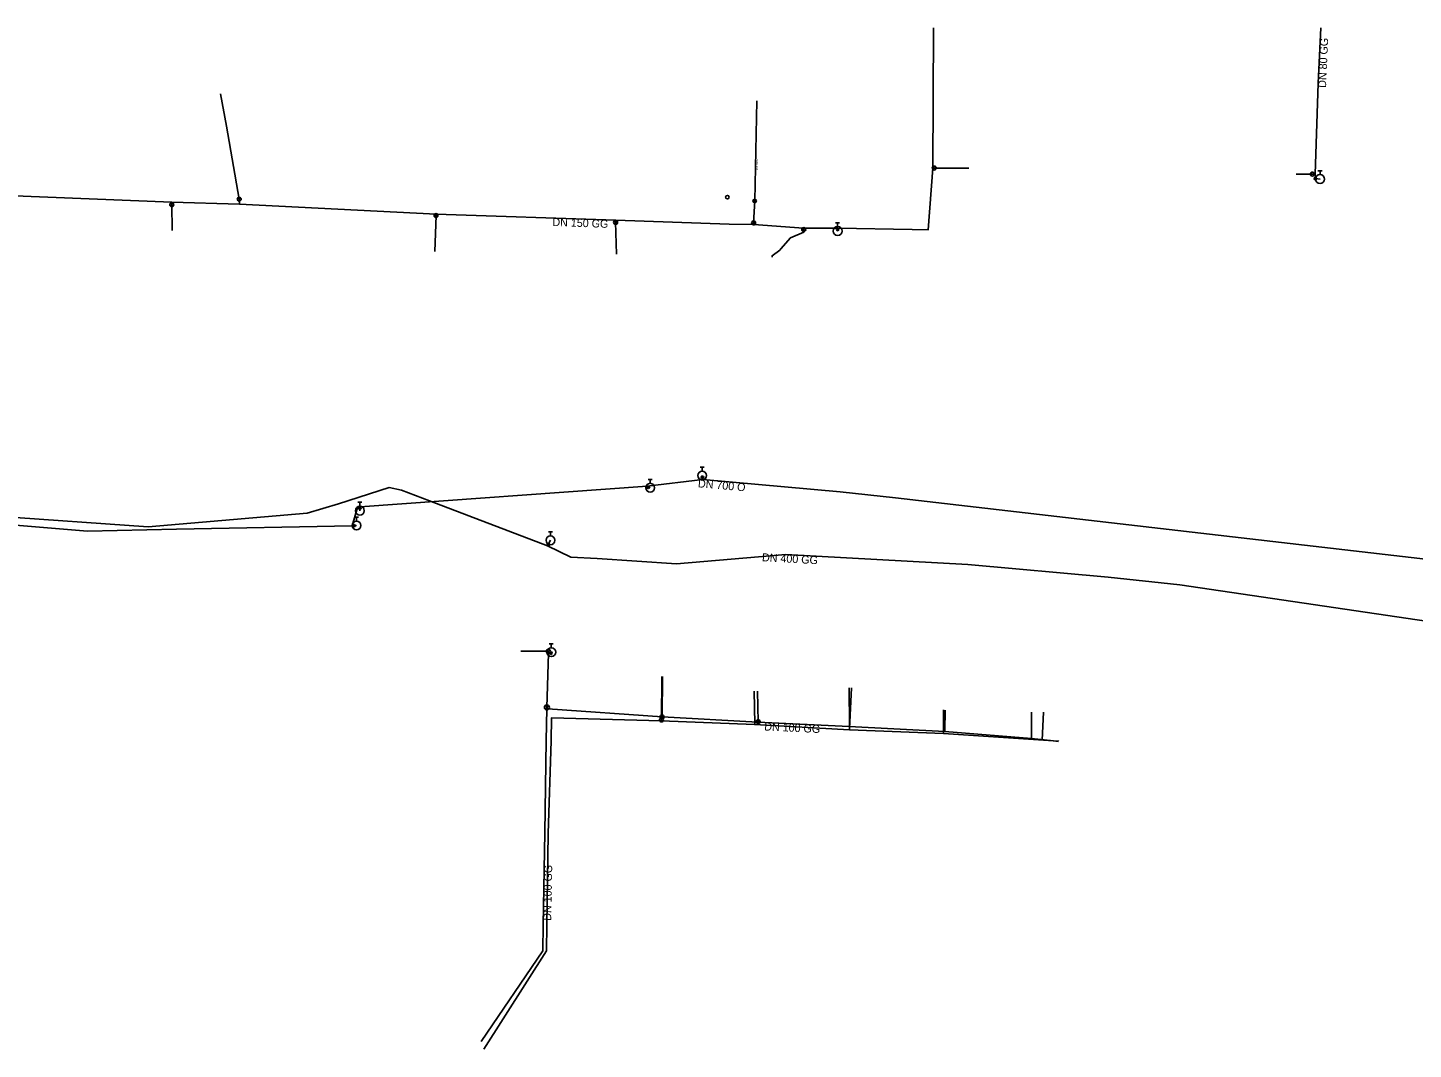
# Model space of a CAD drawing. Extents: x -451355 to -449353, y -1101368 to -1101089.
# Drawn here: x -451062.3 to -450784.4, y -1101294 to -1101089.2 of the extents above; entities that cross this region are included whole.
import ezdxf

# ---------------------------------------------------------------- set-up
doc = ezdxf.new("R2010")
doc.units = 0
for name, color, linetype in [('_hydrantova_odbocka_', 7, 'Continuous'), ('_pripojka_prevzato_z_dokumentace_', 7, 'Continuous'), ('_pripojka_priblizne_', 7, 'Continuous'), ('_voda_smvak_prevzato_z_dokumentace_', 7, 'Continuous'), ('Default', 7, 'Continuous'), ('MoLevel 27', 7, 'Continuous'), ('MoLevel 28', 7, 'Continuous'), ('MoLevel 30', 7, 'Continuous'), ('MoLevel 46', 7, 'Continuous'), ('MoLevel 53', 7, 'Continuous'), ('MoLevel 55', 7, 'Continuous')]:
    doc.layers.add(name, color=color, linetype=linetype)

# ---------------------------------------------------------------- blocks, each defined once
blk = doc.blocks.new('_uzaver_')
at = {"layer": 'Default'}
for p, q in [((-0.000035, -0.000035), (0.000035, 0.000035)), ((0.000035, -0.000035), (-0.000035, 0.000035))]:
    blk.add_line(p, q, dxfattribs=at)
for radius in [0.00005, 0.0000025]:
    blk.add_circle((0, 0), radius, dxfattribs=at)
blk = doc.blocks.new('_uzaver_pripojka_')
at = {"layer": 'Default'}
for p, q in [((-0.000035, -0.000035), (0.000035, 0.000035)), ((0.000035, -0.000035), (-0.000035, 0.000035))]:
    blk.add_line(p, q, dxfattribs=at)
for radius in [0.00005, 0.0000025]:
    blk.add_circle((0, 0), radius, dxfattribs=at)
blk = doc.blocks.new('_hydrant_voda_')
at = {"layer": 'Default'}
for p, q in [((-0.000023, 0.000095), (0.000023, 0.000095)), ((0, 0.000095), (0, 0.00005))]:
    blk.add_line(p, q, dxfattribs=at)
blk.add_circle((0, 0), 0.00005, dxfattribs=at)
blk = doc.blocks.new('_sachta_voda_')
at = {"layer": 'Default'}
blk.add_circle((0, 0), 0.000035, dxfattribs=at)

msp = doc.modelspace()

# ---------------------------------------------------------------- linework, layer by layer
at = {"layer": '_hydrantova_odbocka_'}
for p, q in [((-450804.06, -1101119.44), (-450803.13, -1101119.53)), ((-450957.85, -1101214.57), (-450957.34, -1101214.56)), ((-450957.34, -1101214.56), (-450957.28, -1101214.38))]:
    msp.add_line(p, q, dxfattribs=at)
for points in [[(-450899.84, -1101129.39), (-450899.84, -1101129.63), (-450899.86, -1101129.95)], [(-450938.03, -1101181.08), (-450938.05, -1101181.35), (-450937.85, -1101181.33), (-450937.44, -1101181.41)], [(-450926.89, -1101179.79), (-450926.96, -1101179.31), (-450927.03, -1101178.98)], [(-450995.63, -1101185.21), (-450995.68, -1101185.47), (-450995.66, -1101186.01)], [(-450997.22, -1101189.02), (-450996.84, -1101189.02), (-450996.33, -1101188.99)], [(-450958.04, -1101193.09), (-450957.88, -1101192.79), (-450957.46, -1101191.95)]]:
    msp.add_lwpolyline(points, dxfattribs=at)
at = {"layer": '_pripojka_prevzato_z_dokumentace_'}
for p, q in [((-450916.49, -1101123.92), (-450916.03, -1101103.87)), ((-450962.34, -1101214.2), (-450963.4, -1101214.2)), ((-450935.08, -1101227.36), (-450934.99, -1101219.25))]:
    msp.add_line(p, q, dxfattribs=at)
for points in [[(-451019.78, -1101124.55), (-451019.87, -1101123.57), (-451022.41, -1101108.94), (-451023.59, -1101102.43)], [(-450880.8, -1101117.34), (-450880.5, -1101117.33), (-450873.58, -1101117.32)], [(-450804.12, -1101118.58), (-450804.14, -1101118.58), (-450804.66, -1101118.54), (-450807.94, -1101118.55)], [(-451033.37, -1101124.19), (-451033.39, -1101124.65), (-451033.32, -1101129.83)], [(-450916.66, -1101128.63), (-450916.7, -1101128.31), (-450916.49, -1101123.92)], [(-450980.4, -1101126.55), (-450980.4, -1101126.85), (-450980.66, -1101134.07)], [(-450944.34, -1101127.77), (-450944.38, -1101128.2), (-450944.21, -1101134.61)], [(-450906.69, -1101129.37), (-450906.67, -1101129.66), (-450906.64, -1101130.19), (-450909.32, -1101131.32), (-450911.24, -1101133.55)], [(-450911.24, -1101133.55), (-450911.47, -1101133.81), (-450913, -1101134.89), (-450913.01, -1101135.21)], [(-450957.85, -1101214.57), (-450957.87, -1101214.2), (-450962.34, -1101214.2)], [(-450935.24, -1101228.17), (-450935.19, -1101227.96), (-450935.11, -1101219.25)], [(-450916.51, -1101228.86), (-450916.48, -1101228.71), (-450916.61, -1101222.22)], [(-450915.83, -1101228.39), (-450915.81, -1101228.31), (-450915.9, -1101222.17)], [(-450897.52, -1101229.26), (-450897.51, -1101229.16), (-450897.58, -1101221.5)], [(-450897.5, -1101229.93), (-450897.5, -1101229.75), (-450897.05, -1101221.51)], [(-450878.66, -1101230.68), (-450878.63, -1101230.48), (-450878.63, -1101225.93)], [(-450878.37, -1101230.29), (-450878.36, -1101230.07), (-450878.31, -1101225.97)], [(-450861.01, -1101231.7), (-450861, -1101231.39), (-450861, -1101226.4)]]:
    msp.add_lwpolyline(points, dxfattribs=at)
at = {"layer": '_pripojka_priblizne_'}
msp.add_line((-450858.57, -1101226.38), (-450858.84, -1101232.01), dxfattribs=at)
at = {"layer": '_voda_smvak_prevzato_z_dokumentace_'}
for p, q in [((-450957.85, -1101214.57), (-450958.17, -1101225.45)), ((-450958.17, -1101225.45), (-450958.18, -1101225.73))]:
    msp.add_line(p, q, dxfattribs=at)
for points in [[(-450880.63, -1101089.19), (-450880.8, -1101117.34), (-450881.71, -1101129.74), (-450884.9, -1101129.62), (-450899.84, -1101129.39), (-450906.69, -1101129.37), (-450916.66, -1101128.63), (-450921.61, -1101128.6), (-450944.34, -1101127.77), (-450980.4, -1101126.55), (-451019.78, -1101124.55), (-451033.37, -1101124.19), (-451083.14, -1101122.14), (-451084.29, -1101121.78)], [(-450802.99, -1101089.19), (-450803.48, -1101100.3), (-450804.12, -1101118.58), (-450804.06, -1101119.44)], [(-451068.8, -1101188.58), (-451050.3, -1101190.14), (-451032.45, -1101189.7), (-450997.22, -1101189.02), (-450996.11, -1101185.36), (-450995.63, -1101185.21), (-450938.03, -1101181.08), (-450926.89, -1101179.79), (-450899.38, -1101182.22), (-450888.28, -1101183.45), (-450772.13, -1101196.87)], [(-451068.59, -1101187.08), (-451038.12, -1101189.24), (-451006.24, -1101186.52), (-450999.94, -1101184.64), (-450989.76, -1101181.39), (-450987.33, -1101181.88), (-450981.7, -1101184.05), (-450958.04, -1101193.09), (-450953.39, -1101195.36), (-450948.09, -1101195.61), (-450932.19, -1101196.67), (-450910.27, -1101194.8), (-450873.74, -1101196.81), (-450845.59, -1101199.31), (-450831.24, -1101200.86), (-450754.63, -1101212.14), (-450745.13, -1101214.06)], [(-450958.18, -1101225.73), (-450958.28, -1101232.06), (-450958.56, -1101250.61), (-450958.93, -1101269.01), (-450958.96, -1101274.22), (-450971.36, -1101292.42)], [(-450855.54, -1101232.28), (-450857.15, -1101232.11), (-450861.01, -1101231.7), (-450878.37, -1101230.29), (-450897.52, -1101229.26), (-450915.83, -1101228.39), (-450935.08, -1101227.36), (-450957.96, -1101225.75), (-450958.18, -1101225.73)], [(-450855.54, -1101232.25), (-450855.54, -1101232.2), (-450856.59, -1101232.16), (-450878.66, -1101230.68), (-450897.5, -1101229.93), (-450916.51, -1101228.86), (-450935.24, -1101228.17), (-450957.23, -1101227.52), (-450957.29, -1101232.18), (-450957.91, -1101250.71), (-450958.19, -1101269.04), (-450958.24, -1101274.22), (-450970.83, -1101293.98)]]:
    msp.add_lwpolyline(points, dxfattribs=at)

# ---------------------------------------------------------------- block references
at = {"layer": 'MoLevel 27', "xscale": 5000, "yscale": 5000}
for p in [(-450804.06, -1101119.44), (-450899.84, -1101129.63), (-450995.68, -1101185.47), (-450957.88, -1101192.79), (-450957.34, -1101214.56)]:
    msp.add_blockref('_uzaver_', p, dxfattribs=at)
at = {"layer": 'MoLevel 27'}
for p, xscale, yscale, rotation in [((-450937.85, -1101181.33), 5000, 4999.999999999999, -174.61629722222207), ((-450926.96, -1101179.31), 5000.000000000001, 5000, -80.92363333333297), ((-450996.84, -1101189.02), 5000, 5000.000000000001, -0.45835555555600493), ((-450958.17, -1101225.45), 10000, 10000.000000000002, -4.028702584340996)]:
    msp.add_blockref('_uzaver_', p, dxfattribs=dict(at, xscale=xscale, yscale=yscale, rotation=rotation))
at = {"layer": 'MoLevel 28', "xscale": 17636.68430335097, "yscale": 17636.68430335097}
for p in [(-450803.13, -1101119.53), (-450899.86, -1101129.95), (-450927.03, -1101178.98), (-450937.44, -1101181.41), (-450995.66, -1101186.01), (-450996.33, -1101188.99), (-450957.46, -1101191.95), (-450957.28, -1101214.38)]:
    msp.add_blockref('_hydrant_voda_', p, dxfattribs=at)
at = {"layer": 'MoLevel 30', "xscale": 10000, "yscale": 10000}
for p in [(-450921.97, -1101123.17), (-450916.49, -1101123.92)]:
    msp.add_blockref('_sachta_voda_', p, dxfattribs=at)
at = {"layer": 'MoLevel 53', "xscale": 7999.999999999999, "yscale": 7999.999999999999}
for p in [(-450880.5, -1101117.33), (-450804.66, -1101118.54), (-451019.87, -1101123.57), (-451033.39, -1101124.65), (-450980.4, -1101126.85), (-450944.38, -1101128.2), (-450916.7, -1101128.31), (-450906.67, -1101129.66), (-450957.87, -1101214.2), (-450935.19, -1101227.96), (-450935.08, -1101227.36), (-450915.81, -1101228.31)]:
    msp.add_blockref('_uzaver_pripojka_', p, dxfattribs=at)

# ---------------------------------------------------------------- texts
at = {"layer": 'MoLevel 46'}
for s, rotation, p in [('DN 80 GG', 87.4759, (-450801.92, -1101101.27)), ('DN 150 GG', 358.0623, (-450957.08, -1101128.94)), ('DN 700 O', 354.9461, (-450927.92, -1101181.31)), ('DN 400 GG', 356.8506, (-450915.06, -1101196.14)), ('DN 100 GG', 357.2796, (-450914.6, -1101230.06)), ('DN 100 GG', 88.848, (-450957.31, -1101268.23))]:
    msp.add_text(s, height=1.605, rotation=rotation, dxfattribs=at).set_placement(p)
at = {"layer": 'MoLevel 55'}
msp.add_text('DN 80 L', height=0.455, rotation=88.6827, dxfattribs=at).set_placement((-450915.89, -1101117.79))

doc.saveas('drawing.dxf')
